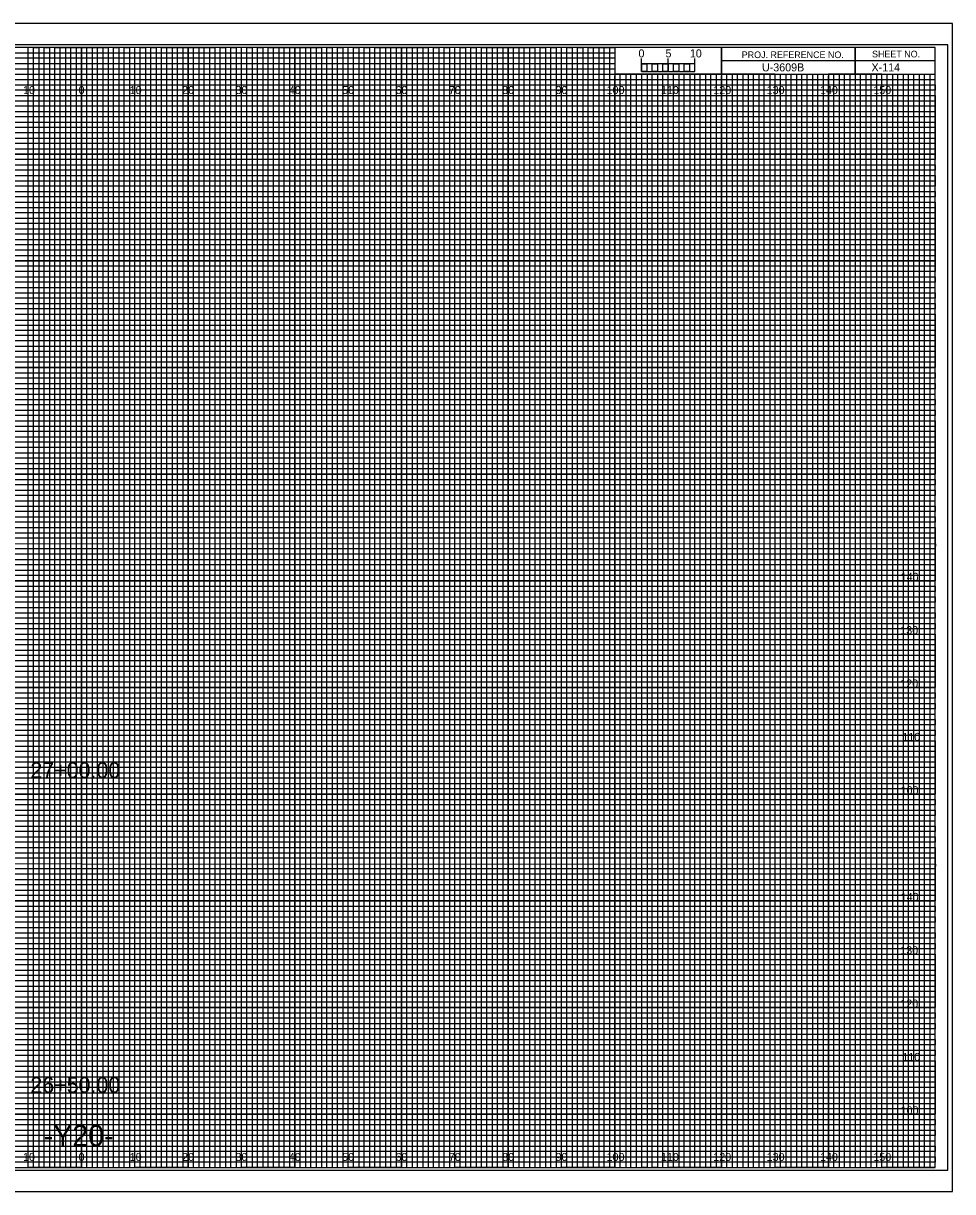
# Model space of a CAD drawing. Extents: x -13 to 323, y -5 to 2634.
# Drawn here: x 149.1 to 323.3, y 2415.5 to 2634.5 of the extents above; entities that cross this region are included whole.
import ezdxf

# ---------------------------------------------------------------- set-up
doc = ezdxf.new("R2010")
doc.units = 0
for name, color, linetype in [('Exist CMT Pavement', 7, 'Continuous'), ('Exist Cross Section Cell', 7, 'Continuous'), ('Exist XS Center Line Elevation Label', 7, 'Continuous'), ('Exist XS Ground Line', 7, 'Continuous'), ('Prop CMT Pvmt Course 1 Wedge', 7, 'Continuous'), ('Prop CMT Pvmt Course 2', 7, 'Continuous'), ('Prop CMT Pvmt Course 2 Wedge', 7, 'Continuous'), ('Prop CMT Pvmt Course 3', 7, 'Continuous'), ('Prop CMT Pvmt Course 3 Wedge', 7, 'Continuous'), ('Prop CMT Pvmt Surface', 7, 'Continuous'), ('Prop CMT Pvmt Wedge Surface 1', 7, 'Continuous'), ('Prop CMT Pvmt Wedge Surface 2', 7, 'Continuous'), ('Prop CMT Shld Paved Course 1', 7, 'Continuous'), ('Prop CMT Shld Paved Course 2', 7, 'Continuous'), ('Prop CMT Shld Paved Course 3', 7, 'Continuous'), ('Prop CMT Subgrade Earthwork', 7, 'Continuous'), ('Scratch_Level_0', 7, 'Continuous')]:
    doc.layers.add(name, color=color, linetype=linetype)

msp = doc.modelspace()

# ---------------------------------------------------------------- linework, layer by layer
at = {"layer": 'Exist XS Center Line Elevation Label'}
for points in [[(145, 2420), (155, 2420), (155, 2630), (165, 2630), (165, 2420), (175, 2420), (175, 2630), (185, 2630), (185, 2420), (195, 2420), (195, 2630), (205, 2630), (205, 2420), (215, 2420), (215, 2630), (225, 2630), (225, 2420), (235, 2420), (235, 2630), (245, 2630), (245, 2420), (255, 2420), (255, 2630), (259.93, 2630), (260, 2630), (260, 2625), (264.99, 2625), (264.99, 2420), (275, 2420), (275, 2625), (285, 2625), (285, 2420), (295, 2420), (295, 2625), (305, 2625), (305, 2420), (315, 2420), (315, 2625)], [(0, 2625), (275, 2625)], [(0, 2605), (320, 2605), (320, 2615), (0, 2615)], [(0, 2585), (320, 2585), (320, 2595), (0, 2595)], [(0, 2565), (320, 2565), (320, 2575), (0, 2575)], [(0, 2545), (320, 2545), (320, 2555), (0, 2555)], [(0, 2525), (320, 2525), (320, 2535), (0, 2535)], [(0, 2505), (320, 2505), (320, 2515), (0, 2515)], [(0, 2485), (320, 2485), (320, 2495), (0, 2495)], [(0, 2465), (320, 2465), (320, 2475), (0, 2475)], [(0, 2445), (320, 2445), (320, 2455), (0, 2455)], [(0, 2425), (320, 2425), (320, 2435), (0, 2435)]]:
    msp.add_lwpolyline(points, dxfattribs=at)
at = {"layer": 'Exist XS Ground Line'}
for p, q in [((150, 2630), (140, 2630)), ((150, 2420), (150, 2630)), ((170, 2630), (160, 2630)), ((160, 2630), (160, 2420)), ((170, 2420), (170, 2630)), ((190, 2630), (180, 2630)), ((180, 2630), (180, 2420)), ((190, 2420), (190, 2630)), ((210, 2630), (200, 2630)), ((200, 2630), (200, 2420)), ((210, 2420), (210, 2630)), ((230, 2630), (220, 2630)), ((220, 2630), (220, 2420)), ((230, 2420), (230, 2630)), ((250, 2630), (240, 2630)), ((240, 2630), (240, 2420)), ((250, 2420), (250, 2630)), ((260, 2630), (260, 2420)), ((270, 2420), (270, 2625)), ((290, 2625), (280, 2625)), ((280, 2625), (280, 2420)), ((290, 2420), (290, 2625)), ((310, 2625), (300, 2625)), ((300, 2625), (300, 2420)), ((310, 2420), (310, 2625)), ((160, 2420), (150, 2420)), ((180, 2420), (170, 2420)), ((200, 2420), (190, 2420)), ((220, 2420), (210, 2420)), ((240, 2420), (230, 2420)), ((260, 2420), (250, 2420)), ((280, 2420), (270, 2420)), ((300, 2420), (290, 2420)), ((320, 2420), (310, 2420)), ((320, 2420), (320, 2420))]:
    msp.add_line(p, q, dxfattribs=at)
for points in [[(0, 2620), (320, 2620), (320, 2610), (0, 2610)], [(0, 2600), (320, 2600), (320, 2590), (0, 2590)], [(0, 2580), (320, 2580), (320, 2570), (0, 2570)], [(0, 2560), (320, 2560), (320, 2550), (0, 2550)], [(0, 2540), (320, 2540), (320, 2530), (0, 2530)], [(0, 2520), (320, 2520), (320, 2510), (0, 2510)], [(0, 2500), (320, 2500), (320, 2490), (0, 2490)], [(0, 2480), (320, 2480), (320, 2470), (0, 2470)], [(0, 2460), (320, 2460), (320, 2450), (0, 2450)], [(0, 2440), (320, 2440), (320, 2430), (0, 2430)]]:
    msp.add_lwpolyline(points, dxfattribs=at)
at = {"layer": 'Prop CMT Pvmt Course 1 Wedge'}
for p, q in [((323.3, 2634.5), (-13.4, 2634.5)), ((-13.4, 2415.5), (323.3, 2415.5))]:
    msp.add_line(p, q, dxfattribs=at)
at = {"layer": 'Prop CMT Pvmt Course 2'}
msp.add_lwpolyline([(-13.4, 2415.5), (323.3, 2415.5), (323.3, 2634.5), (-13.4, 2634.5)], close=True, dxfattribs=at)
at = {"layer": 'Prop CMT Pvmt Course 3'}
msp.add_lwpolyline([(-10.8, 2419.5), (322.4, 2419.5), (322.4, 2630.5), (-10.8, 2630.5)], close=True, dxfattribs=at)
at = {"layer": 'Prop CMT Shld Paved Course 1'}
for p, q in [((305, 2630), (305, 2625)), ((305, 2625), (305, 2630)), ((280, 2627.5), (280, 2625)), ((320, 2627.49), (280, 2627.49)), ((280, 2625), (320, 2625))]:
    msp.add_line(p, q, dxfattribs=at)
for points in [[(320, 2630), (0, 2630), (0, 2420), (320, 2420)], [(280, 2630), (260, 2630), (260, 2625.03), (280, 2625.03)], [(320, 2630), (280, 2630), (280, 2625), (320, 2625)]]:
    msp.add_lwpolyline(points, close=True, dxfattribs=at)
at = {"layer": 'Prop CMT Shld Paved Course 2'}
for p, q in [((267, 2625), (266.01, 2625)), ((266.01, 2625), (266.01, 2420)), ((267, 2420), (267, 2625)), ((269, 2625), (268, 2625)), ((268, 2625), (268, 2420)), ((269, 2420), (269, 2625)), ((266.01, 2420), (265, 2420)), ((268, 2420), (267, 2420))]:
    msp.add_line(p, q, dxfattribs=at)
for points in [[(150, 2420), (151, 2420), (151, 2630), (152, 2630), (152, 2420)], [(152, 2420), (153, 2420), (153, 2630), (154, 2630), (154, 2420)], [(155, 2420), (156, 2420), (156, 2630), (157, 2630), (157, 2420)], [(157, 2420), (158, 2420), (158, 2630), (159, 2630), (159, 2420)], [(160, 2420), (161, 2420), (161, 2630), (162, 2630), (162, 2420)], [(162, 2420), (163, 2420), (163, 2630), (164, 2630), (164, 2420)], [(165, 2420), (166, 2420), (166, 2630), (167, 2630), (167, 2420)], [(167, 2420), (168, 2420), (168, 2630), (169, 2630), (169, 2420)], [(170, 2420), (171, 2420), (171, 2630), (172, 2630), (172, 2420)], [(172, 2420), (173, 2420), (173, 2630), (174, 2630), (174, 2420)], [(175, 2420), (176, 2420), (176, 2630), (177, 2630), (177, 2420)], [(177, 2420), (178, 2420), (178, 2630), (179, 2630), (179, 2420)], [(180, 2420), (181, 2420), (181, 2630), (182, 2630), (182, 2420)], [(182, 2420), (183, 2420), (183, 2630), (184, 2630), (184, 2420)], [(185, 2420), (186, 2420), (186, 2630), (187, 2630), (187, 2420)], [(187, 2420), (188, 2420), (188, 2630), (189, 2630), (189, 2420)], [(190, 2420), (191, 2420), (191, 2630), (192, 2630), (192, 2420)], [(192, 2420), (193, 2420), (193, 2630), (194, 2630), (194, 2420)], [(195, 2420), (196, 2420), (196, 2630), (197, 2630), (197, 2420)], [(197, 2420), (198, 2420), (198, 2630), (199, 2630), (199, 2420)], [(200, 2420), (201, 2420), (201, 2630), (202, 2630), (202, 2420)], [(202, 2420), (203, 2420), (203, 2630), (204, 2630), (204, 2420)], [(205, 2420), (206, 2420), (206, 2630), (207, 2630), (207, 2420)], [(207, 2420), (208, 2420), (208, 2630), (209, 2630), (209, 2420)], [(210, 2420), (211, 2420), (211, 2630), (212, 2630), (212, 2420)], [(212, 2420), (213, 2420), (213, 2630), (214, 2630), (214, 2420)], [(215, 2420), (216, 2420), (216, 2630), (217, 2630), (217, 2420)], [(217, 2420), (218, 2420), (218, 2630), (219, 2630), (219, 2420)], [(220, 2420), (221, 2420), (221, 2630), (222, 2630), (222, 2420)], [(222, 2420), (223, 2420), (223, 2630), (224, 2630), (224, 2420)], [(225, 2420), (226, 2420), (226, 2630), (227, 2630), (227, 2420)], [(227, 2420), (228, 2420), (228, 2630), (229, 2630), (229, 2420)], [(230, 2420), (231, 2420), (231, 2630), (232, 2630), (232, 2420)], [(232, 2420), (233, 2420), (233, 2630), (234, 2630), (234, 2420)], [(235, 2420), (236, 2420), (236, 2630), (237, 2630), (237, 2420)], [(237, 2420), (238, 2420), (238, 2630), (239, 2630), (239, 2420)], [(240, 2420), (241, 2420), (241, 2630), (242, 2630), (242, 2420)], [(242, 2420), (243, 2420), (243, 2630), (244, 2630), (244, 2420)], [(245, 2420), (246, 2420), (246, 2630), (247, 2630), (247, 2420)], [(247, 2420), (248, 2420), (248, 2630), (249, 2630), (249, 2420)], [(250, 2420), (251, 2420), (251, 2630), (252, 2630), (252, 2420)], [(252, 2420), (253, 2420), (253, 2630), (254, 2630), (254, 2420)], [(255, 2420), (256, 2420), (256, 2630), (257, 2630), (257, 2420)], [(257, 2420), (258, 2420), (258, 2630), (259, 2630), (259, 2420)], [(260, 2420), (261, 2420), (261, 2625), (262.02, 2625), (262.02, 2420)], [(262, 2420), (263, 2420), (263, 2625), (263.99, 2625), (263.99, 2420)], [(270, 2420), (270.98, 2420), (270.98, 2625), (272, 2625), (272, 2420)], [(272, 2420), (273, 2420), (273, 2625), (274.05, 2625), (274.05, 2420)], [(275, 2420), (276, 2420), (276, 2625), (277, 2625), (277, 2420)], [(277, 2420), (278, 2420), (278, 2625), (279, 2625), (279, 2420)], [(280, 2420), (281, 2420), (281, 2625), (282, 2625), (282, 2420)], [(282, 2420), (283, 2420), (283, 2625), (284, 2625), (284, 2420)], [(285, 2420), (286, 2420), (286, 2625), (287, 2625), (287, 2420)], [(287, 2420), (288, 2420), (288, 2625), (289, 2625), (289, 2420)], [(290, 2420), (291, 2420), (291, 2625), (292, 2625), (292, 2420)], [(292, 2420), (293, 2420), (293, 2625), (294, 2625), (294, 2420)], [(295, 2420), (296, 2420), (296, 2625), (297, 2625), (297, 2420)], [(297, 2420), (298, 2420), (298, 2625), (299, 2625), (299, 2420)], [(300, 2420), (301, 2420), (301, 2625), (302, 2625), (302, 2420)], [(302, 2420), (303, 2420), (303, 2625), (304, 2625), (304, 2420)], [(305, 2420), (306, 2420), (306, 2625), (307, 2625), (307, 2420)], [(307, 2420), (308, 2420), (308, 2625), (309, 2625), (309, 2420)], [(310, 2420), (311, 2420), (311, 2625), (312, 2625), (312, 2420)], [(312, 2420), (313, 2420), (313, 2625), (314, 2625), (314, 2420)], [(315, 2420), (316, 2420), (316, 2625), (317, 2625), (317, 2420)], [(317, 2420), (318, 2420), (318, 2625), (319, 2625), (319, 2420)]]:
    msp.add_lwpolyline(points, dxfattribs=at)
at = {"layer": 'Prop CMT Shld Paved Course 3'}
for p, q in [((265, 2625.49), (265, 2627.9)), ((265, 2626.9), (265, 2627.9)), ((270, 2625.49), (270, 2627.9)), ((275, 2625.49), (275, 2627.9)), ((275, 2626.9), (275, 2627.9))]:
    msp.add_line(p, q, dxfattribs=at)
for points in [[(275, 2626.9), (265, 2626.9), (265, 2625.49), (275, 2625.49)], [(265, 2626.9), (266, 2626.9), (266, 2625.49), (265, 2625.49)], [(267, 2626.9), (268, 2626.9), (268, 2625.49), (267, 2625.49)], [(269, 2626.9), (270, 2626.9), (270, 2625.49), (269, 2625.49)], [(271, 2626.9), (272, 2626.9), (272, 2625.49), (271, 2625.49)], [(273, 2626.9), (274, 2626.9), (274, 2625.49), (273, 2625.49)]]:
    msp.add_lwpolyline(points, close=True, dxfattribs=at)
at = {"layer": 'Prop CMT Subgrade Earthwork'}
for p, q in [((150, 2420), (150, 2630)), ((160, 2420), (160, 2630)), ((170, 2420), (170, 2630)), ((180, 2420), (180, 2630)), ((190, 2420), (190, 2630)), ((200, 2420), (200, 2630)), ((210, 2420), (210, 2630)), ((220, 2420), (220, 2630)), ((230, 2420), (230, 2630)), ((240, 2420), (240, 2630)), ((250, 2420), (250, 2630)), ((260, 2420), (260, 2624.69)), ((270, 2420), (270, 2624.69)), ((280, 2420), (280, 2624.69)), ((290, 2420), (290, 2624.69)), ((300, 2420), (300, 2624.69)), ((310, 2420), (310, 2624.69)), ((0, 2620), (320, 2620)), ((0, 2610), (320, 2610)), ((0, 2600), (320, 2600)), ((0, 2590), (320, 2590)), ((0, 2580), (320, 2580)), ((0, 2570), (320, 2570)), ((0, 2560), (320, 2560)), ((0, 2550), (320, 2550)), ((0, 2540), (320, 2540)), ((0, 2530), (320, 2530)), ((0, 2520), (320, 2520)), ((0, 2510), (320, 2510)), ((0, 2500), (320, 2500)), ((0, 2490), (320, 2490)), ((0, 2480), (320, 2480)), ((0, 2470), (320, 2470)), ((0, 2460), (320, 2460)), ((0, 2450), (320, 2450)), ((0, 2440), (320, 2440)), ((0, 2430), (320, 2430))]:
    msp.add_line(p, q, dxfattribs=at)
at = {"layer": 'Scratch_Level_0'}
for p, q in [((0, 2629), (260, 2629)), ((260, 2629), (260, 2627.98)), ((260, 2627.98), (0, 2627.98)), ((0, 2627), (260, 2627)), ((260, 2625.89), (0, 2625.89)), ((260, 2627), (260, 2625.89)), ((0, 2624), (320, 2624))]:
    msp.add_line(p, q, dxfattribs=at)
for points in [[(0, 2623), (270, 2623), (320, 2623), (320, 2622), (0, 2622)], [(0, 2621), (320, 2621), (320, 2619), (0, 2619)], [(0, 2618), (320, 2618), (320, 2617), (0, 2616.98)], [(0, 2616), (320, 2616), (320, 2614), (0, 2614)], [(0, 2613), (320, 2613), (320, 2612), (0, 2612)], [(0, 2611), (320, 2611), (320, 2609), (0, 2609)], [(0, 2608), (320, 2608), (320, 2607), (0, 2607)], [(0, 2606), (320, 2606), (320, 2604), (0, 2604)], [(0, 2603), (320, 2603), (320, 2602), (0, 2602)], [(0, 2601), (320, 2601), (320, 2599), (0, 2599)], [(0, 2598), (320, 2598), (320, 2597), (0, 2597)], [(0, 2596), (320, 2596), (320, 2593.95), (320, 2593), (320, 2592), (0, 2592)], [(0, 2594), (320, 2594), (320, 2593), (0, 2593)], [(0, 2591), (320, 2591), (320, 2589), (0, 2589.03)], [(0, 2589.03), (320, 2589), (320, 2588), (0, 2588)], [(0, 2587), (320, 2587), (320, 2586), (0, 2586)], [(0, 2584), (320, 2584), (320, 2583), (0, 2583)], [(0, 2582), (320, 2582), (320, 2581), (0, 2581)], [(-0.07, 2578.89), (320, 2578.89), (320, 2577.88), (-0.07, 2577.88)], [(0, 2577), (320, 2577), (320, 2576), (0, 2576)], [(0, 2574), (320, 2574), (320, 2573), (0, 2573)], [(0, 2572), (320, 2572), (320, 2571), (0, 2571)], [(0, 2569), (320, 2569), (320, 2568), (0, 2568)], [(0, 2567), (320, 2567), (320, 2566), (0, 2566)], [(0, 2564), (320, 2564), (320, 2563), (0, 2563)], [(0, 2562), (320, 2562), (320, 2561), (0, 2561)], [(0, 2559), (320, 2559), (319.99, 2557.98), (0, 2558)], [(0, 2557), (320, 2557), (320, 2556), (0, 2556)], [(0, 2554), (320, 2554), (320, 2553), (0, 2553)], [(0, 2552), (320, 2552), (320, 2551), (0, 2551)], [(0, 2549), (320, 2549), (320, 2548), (0, 2548)], [(0, 2547), (320, 2547), (320, 2546), (0, 2546)], [(0, 2544), (320, 2544), (320, 2543), (0, 2543)], [(0, 2542), (320, 2542), (320, 2541), (0, 2541)], [(0, 2539), (320, 2539), (320, 2538), (0, 2538)], [(0, 2536.99), (320.07, 2536.91), (320, 2536), (0, 2536)], [(0, 2534), (320, 2534), (320, 2533), (0, 2533)], [(0, 2532), (320, 2532), (320, 2531), (0, 2531)], [(0, 2529), (320, 2529), (320, 2528), (0, 2528)], [(0, 2527), (320, 2527), (320, 2526), (0, 2526)], [(0, 2524), (320, 2524), (320, 2523), (0, 2523)], [(0, 2522), (320, 2522), (320, 2521), (0, 2521)], [(0, 2519), (320, 2519), (320, 2518), (0, 2518)], [(0, 2517), (320, 2517), (320, 2516), (0, 2516)], [(0, 2514), (320, 2514), (320, 2513), (0, 2513)], [(0, 2512), (320, 2512), (320, 2511), (0, 2511)], [(0, 2509), (320, 2509), (320, 2508), (0, 2508)], [(0, 2507), (320, 2507), (320, 2506), (0, 2506)], [(0, 2504), (320, 2504), (320, 2503), (0, 2503)], [(0, 2502), (320, 2502), (320, 2501), (0, 2501)], [(0, 2499), (320, 2499), (319.99, 2497.98), (0, 2498)], [(0, 2497), (320, 2497), (320, 2496), (0, 2496)], [(0, 2494), (320, 2494), (320, 2493), (0, 2493)], [(0, 2492), (320, 2492), (320, 2491), (0, 2491)], [(0, 2489), (320, 2489), (320, 2488), (0, 2488)], [(0, 2487), (320, 2487), (320, 2486), (0, 2486)], [(0, 2484), (320, 2484), (320, 2483), (0, 2483)], [(0, 2482), (320, 2482), (320, 2481), (0, 2481)], [(0, 2479), (320, 2479), (320, 2478), (0, 2478)], [(0, 2476.99), (320.07, 2476.91), (320, 2476), (0, 2476)], [(0, 2474), (320, 2474), (320, 2473), (0, 2473)], [(0, 2472), (320, 2472), (320, 2471), (0, 2471)], [(0, 2469), (320, 2469), (320, 2468), (0, 2468)], [(0, 2467), (320, 2467), (320, 2466), (0, 2466)], [(0, 2464), (320, 2464), (320, 2463), (0, 2463)], [(0, 2462), (320, 2462), (320, 2461), (0, 2461)], [(0, 2459), (320, 2459), (320, 2458), (0, 2458)], [(0, 2457), (320, 2457), (320, 2456), (0, 2456)], [(0, 2454), (320, 2454), (320, 2453), (0, 2453)], [(0, 2452), (320, 2452), (320, 2451), (0, 2451)], [(0, 2449), (320, 2449), (320, 2448), (0, 2448)], [(0, 2447), (320, 2447), (320, 2446), (0, 2446)], [(0, 2444), (320, 2444), (320, 2443), (0, 2443)], [(0, 2442), (320, 2442), (320, 2441), (0, 2441)], [(0, 2439), (320, 2439), (320, 2438), (0, 2438)], [(0, 2437), (320, 2437), (320, 2436), (0, 2436)], [(0, 2434), (320, 2434), (320, 2433), (0, 2433)], [(0, 2432), (320, 2432), (320, 2431), (0, 2431)], [(0, 2429), (320, 2429), (320, 2428), (0, 2428)], [(0, 2427), (320, 2427), (320, 2426), (0, 2426)], [(0, 2424), (320, 2424), (320, 2423), (0, 2423)], [(0, 2422), (320, 2422), (320, 2421), (0, 2421)]]:
    msp.add_lwpolyline(points, dxfattribs=at)

# ---------------------------------------------------------------- texts
at = {"layer": 'Exist CMT Pavement'}
msp.add_text('X-114', height=1.5, dxfattribs=at).set_placement((308.09, 2625.5))
at = {"layer": 'Exist Cross Section Cell'}
for s, p in [('10', (149.04, 2621.25)), ('0', (159.45, 2621.25)), ('0', (159.45, 2621.25)), ('10', (169.04, 2621.25)), ('20', (178.86, 2621.25)), ('30', (188.86, 2621.25)), ('40', (198.86, 2621.25)), ('50', (208.86, 2621.25)), ('60', (218.86, 2621.25)), ('70', (228.86, 2621.25)), ('80', (238.86, 2621.25)), ('90', (248.86, 2621.25)), ('100', (258.44, 2621.25)), ('110', (268.62, 2621.25)), ('120', (278.44, 2621.25)), ('130', (288.44, 2621.25)), ('140', (298.44, 2621.25)), ('150', (308.44, 2621.25)), ('10', (149.04, 2421.25)), ('0', (159.45, 2421.25)), ('0', (159.45, 2421.25)), ('10', (169.04, 2421.25)), ('20', (178.86, 2421.25)), ('30', (188.86, 2421.25)), ('40', (198.86, 2421.25)), ('50', (208.86, 2421.25)), ('60', (218.86, 2421.25)), ('70', (228.86, 2421.25)), ('80', (238.86, 2421.25)), ('90', (248.86, 2421.25)), ('100', (258.44, 2421.25)), ('110', (268.62, 2421.25)), ('120', (278.44, 2421.25)), ('130', (288.44, 2421.25)), ('140', (298.44, 2421.25)), ('150', (308.44, 2421.25))]:
    msp.add_text(s, height=1.5, dxfattribs=at).set_placement(p)
at = {"layer": 'Prop CMT Pvmt Course 2 Wedge'}
for s, p in [('140', (313.57, 2530)), ('130', (313.49, 2520)), ('120', (313.5, 2510)), ('110', (313.88, 2500)), ('100', (313.55, 2490)), ('140', (313.57, 2470)), ('130', (313.49, 2460)), ('120', (313.5, 2450)), ('110', (313.88, 2440)), ('100', (313.55, 2430))]:
    msp.add_text(s, height=1.5, dxfattribs=at).set_placement(p)
at = {"layer": 'Prop CMT Pvmt Course 3 Wedge'}
for s, p in [('27+00.00', (150.41, 2493)), ('26+50.00', (150.41, 2434))]:
    msp.add_text(s, height=3, dxfattribs=at).set_placement(p)
at = {"layer": 'Prop CMT Pvmt Surface'}
msp.add_text('U-3609B', height=1.5, dxfattribs=at).set_placement((287.56, 2625.5))
at = {"layer": 'Prop CMT Pvmt Wedge Surface 1'}
msp.add_text('-Y20-', height=4, dxfattribs=at).set_placement((152.93, 2424))
at = {"layer": 'Prop CMT Pvmt Wedge Surface 2'}
for s, p in [('5', (269.47, 2628.12)), ('10', (274.04, 2628.12))]:
    msp.add_text(s, height=1.5, dxfattribs=at).set_placement(p)
at = {"layer": 'Prop CMT Shld Paved Course 1'}
for s, p in [('PROJ. REFERENCE NO.', (283.77, 2627.99)), ('SHEET NO.', (308.19, 2628.12))]:
    msp.add_text(s, height=1.25, dxfattribs=at).set_placement(p)
at = {"layer": 'Prop CMT Shld Paved Course 3'}
msp.add_text('0', height=1.5, dxfattribs=at).set_placement((264.41, 2628.12))

doc.saveas('drawing.dxf')
